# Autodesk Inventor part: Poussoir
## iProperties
Created: 2011-01
Part Number: Poussoir
Document SubType Name: Modeling
Designer: eric
Density: 1 g/cm^3
Mass: 2.34244 g
Surface Area: 10.9725 cm^2
Volume: 2.34244 cm^3
Author: eric
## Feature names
1. Base1
